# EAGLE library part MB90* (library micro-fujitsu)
F2MC-16LX MB90385 Series; 16-bit Proprietary Microcontroller CMOS MB90387/387S/F387/F387S/MB90V495G www.fma.fujitsu.com/pdf/e713717.pdf
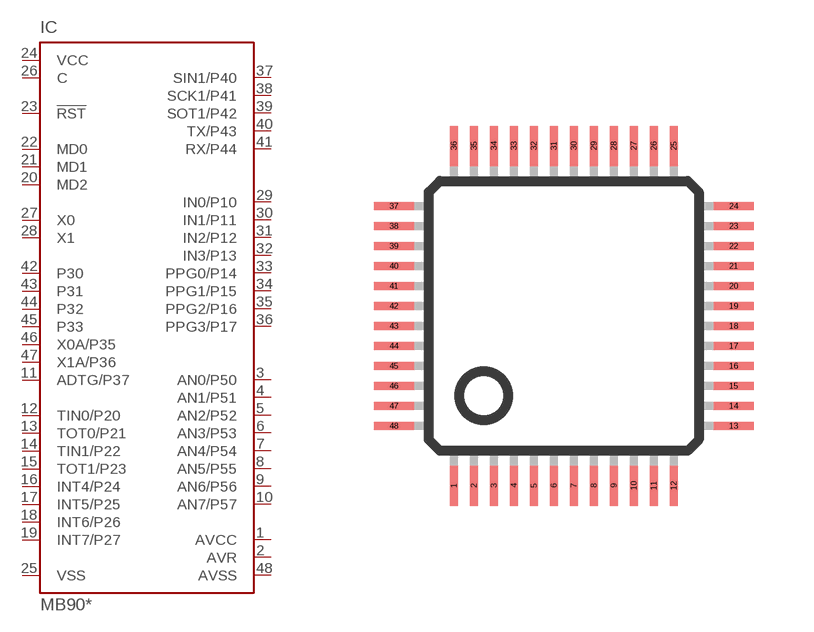
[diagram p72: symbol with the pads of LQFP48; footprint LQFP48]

Designator prefix IC

## MB90387PMT (OC_FARNELL: unknown; OC_NEWARK: unknown), MB90387SPMT (OC_FARNELL: unknown; OC_NEWARK: unknown), MB90F387PMT (OC_FARNELL: unknown; OC_NEWARK: unknown), MB90F387SPMT (OC_FARNELL: unknown; OC_NEWARK: unknown)  [LQFP48]
1  AVCC  pwr
2  AVR  in
3  AN0/P50  in
4  AN1/P51  in
5  AN2/P52  in
6  AN3/P53  in
7  AN4/P54  in
8  AN5/P55  in
9  AN6/P56  in
10  AN7/P57  in
11  ADTG/P37
12  TIN0/P20
13  TOT0/P21
14  TIN1/P22
15  TOT1/P23
16  INT4/P24
17  INT5/P25
18  INT6/P26
19  INT7/P27
20  MD2  in
21  MD1  in
22  MD0  in
23  !RST  in
24  VCC  pwr
25  VSS  pwr
26  C  in
27  X0
28  X1
29  IN0/P10
30  IN1/P11
31  IN2/P12
32  IN3/P13
33  PPG0/P14
34  PPG1/P15
35  PPG2/P16
36  PPG3/P17
37  SIN1/P40
38  SCK1/P41
39  SOT1/P42
40  TX/P43
41  RX/P44
42  P30
43  P31
44  P32
45  P33
46  X0A/P35
47  X1A/P36
48  AVSS  pwr

## Footprint LQFP48 (pad centres in mm)
48-pin plastic LQFP (FPT-48P-M26) www.fma.fujitsu.com/pdf/e713717.pdf
smd 0.2 x 1: 1 -2.75,-4.25; 2 -2.25,-4.25; 3 -1.75,-4.25; 4 -1.25,-4.25; 5 -0.75,-4.25; 6 -0.25,-4.25; 7 0.25,-4.25; 8 0.75,-4.25; 9 1.25,-4.25; 10 1.75,-4.25; 11 2.25,-4.25; 12 2.75,-4.25; 25 2.75,4.25; 26 2.25,4.25; 27 1.75,4.25; 28 1.25,4.25; 29 0.75,4.25; 30 0.25,4.25; 31 -0.25,4.25; 32 -0.75,4.25; 33 -1.25,4.25; 34 -1.75,4.25; 35 -2.25,4.25; 36 -2.75,4.25
smd 1 x 0.2: 13 4.25,-2.75; 14 4.25,-2.25; 15 4.25,-1.75; 16 4.25,-1.25; 17 4.25,-0.75; 18 4.25,-0.25; 19 4.25,0.25; 20 4.25,0.75; 21 4.25,1.25; 22 4.25,1.75; 23 4.25,2.25; 24 4.25,2.75; 37 -4.25,2.75; 38 -4.25,2.25; 39 -4.25,1.75; 40 -4.25,1.25; 41 -4.25,0.75; 42 -4.25,0.25; 43 -4.25,-0.25; 44 -4.25,-0.75; 45 -4.25,-1.25; 46 -4.25,-1.75; 47 -4.25,-2.25; 48 -4.25,-2.75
